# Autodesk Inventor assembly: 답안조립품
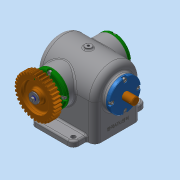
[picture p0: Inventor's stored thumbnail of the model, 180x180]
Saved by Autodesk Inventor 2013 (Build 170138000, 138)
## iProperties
Created: 2019-05
Part Number: 답안조립품
Document SubType Name: Assembly
Designer: dgall
Mass: 2023.51 g
Surface Area: 1805.89 cm^2
Volume: 591.184 cm^3
Density: 3.42281 g/cm^3
Author: dgall
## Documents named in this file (16)
- C:\Users\dgall\Desktop\390504V1041\답안조립품.iam
- C:\Users\dgall\Desktop\390504V1041\본체.ipt
- C:\Users\dgall\Desktop\390504V1041\편심축.ipt
- C:\Users\dgall\Desktop\390504V1041\키 4x4x14.ipt
- C:\Users\dgall\Desktop\390504V1041\베어링 6203.ipt
- C:\Users\dgall\Desktop\390504V1041\볼트 M4x8.ipt
- C:\Users\dgall\Desktop\390504V1041\오일 실 17 32 8.ipt
- C:\Users\dgall\Desktop\390504V1041\커버 A.ipt
- C:\Users\dgall\Desktop\390504V1041\커버 B.ipt
- C:\Users\dgall\Desktop\390504V1041\스퍼기어.ipt
- C:\Users\dgall\Desktop\390504V1041\볼트 M4x10.ipt
- C:\Users\dgall\Desktop\390504V1041\스프링와셔.ipt
- C:\Users\dgall\Desktop\390504V1041\평와셔.ipt
- C:\Users\dgall\Desktop\390504V1041\가이드부시.ipt
- C:\Users\dgall\Desktop\390504V1041\가변스프링.ipt
- C:\Users\dgall\Desktop\390504V1041\슬라이더.ipt
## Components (2 placed, 2 different names)
1. 가이드부시:1
2. 가변스프링:1
